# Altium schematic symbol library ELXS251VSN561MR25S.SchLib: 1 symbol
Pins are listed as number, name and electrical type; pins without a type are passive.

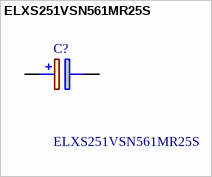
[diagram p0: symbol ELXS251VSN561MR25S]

## ELXS251VSN561MR25S
designator C?
Nippon Chemi-Con 560uF 250 V dc Aluminium Electrolytic Capacitor, LXS Series 5000h 30 (Dia.) x 25mm; Geometry.Height: 27.5mm
footprint CAPPRD1000W180D3050H2750
pins: 1 +, 2 -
